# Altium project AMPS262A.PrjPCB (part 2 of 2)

## Sheet AMPS262A_SPDIF_I2S_PSIA.SchDoc
size A2; Date: Not shown in title block; ApprovedBy: Not shown in title block; CheckedBy: Not shown in title block; Author: Not shown in title block; CompanyName: Not shown in title block; Engineer: Not shown in title block; Organization: Not shown in title block; Address1: Not shown in title block; Address2: Not shown in title block; Address3: Not shown in title block; Address4: Not shown in title block; DocumentNumber: 2; Revision: Use project parameter SCH_Rev; SheetNumber: 4; SheetTotal: 5; PageSetup: Record=PageOptions¦CenterHorizontal=True¦CenterVertical=True¦PrintScale=1.00¦XCorrection=1.00¦YCorrection=1.00¦PrintKind=0¦BorderSize=5000000¦LeftOffset=0¦BottomOffset=0¦Orientation=2¦PaperLength=1000¦PaperWidth=1000¦Scale=100¦PaperSource=15¦PrintQuality=600¦MediaType=1¦DitherType=10¦PaperKind=Letter¦PrintScaleMode=1
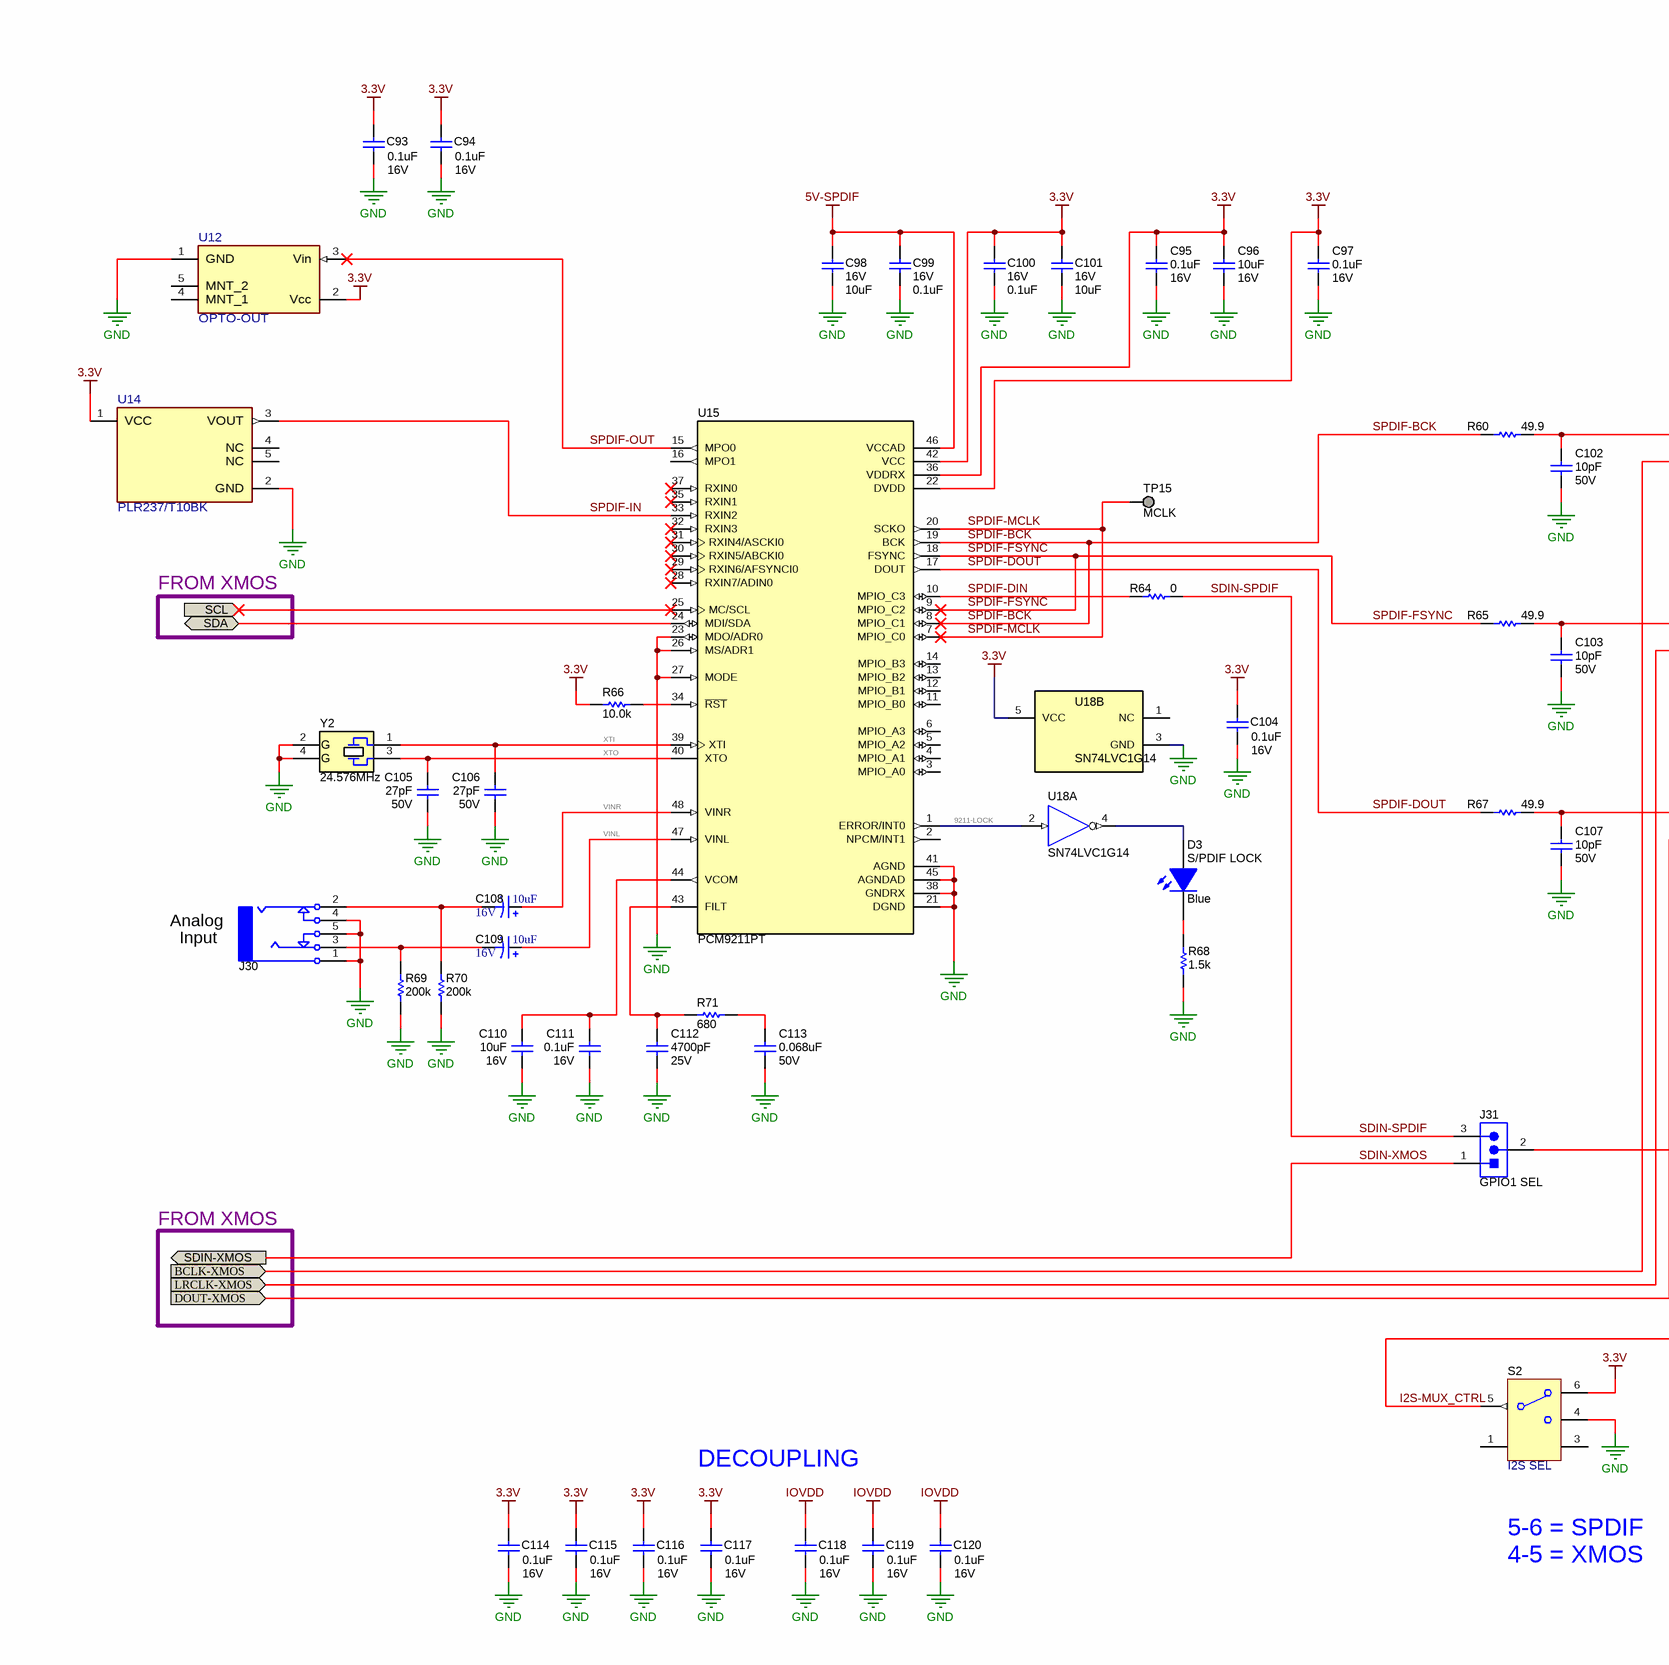
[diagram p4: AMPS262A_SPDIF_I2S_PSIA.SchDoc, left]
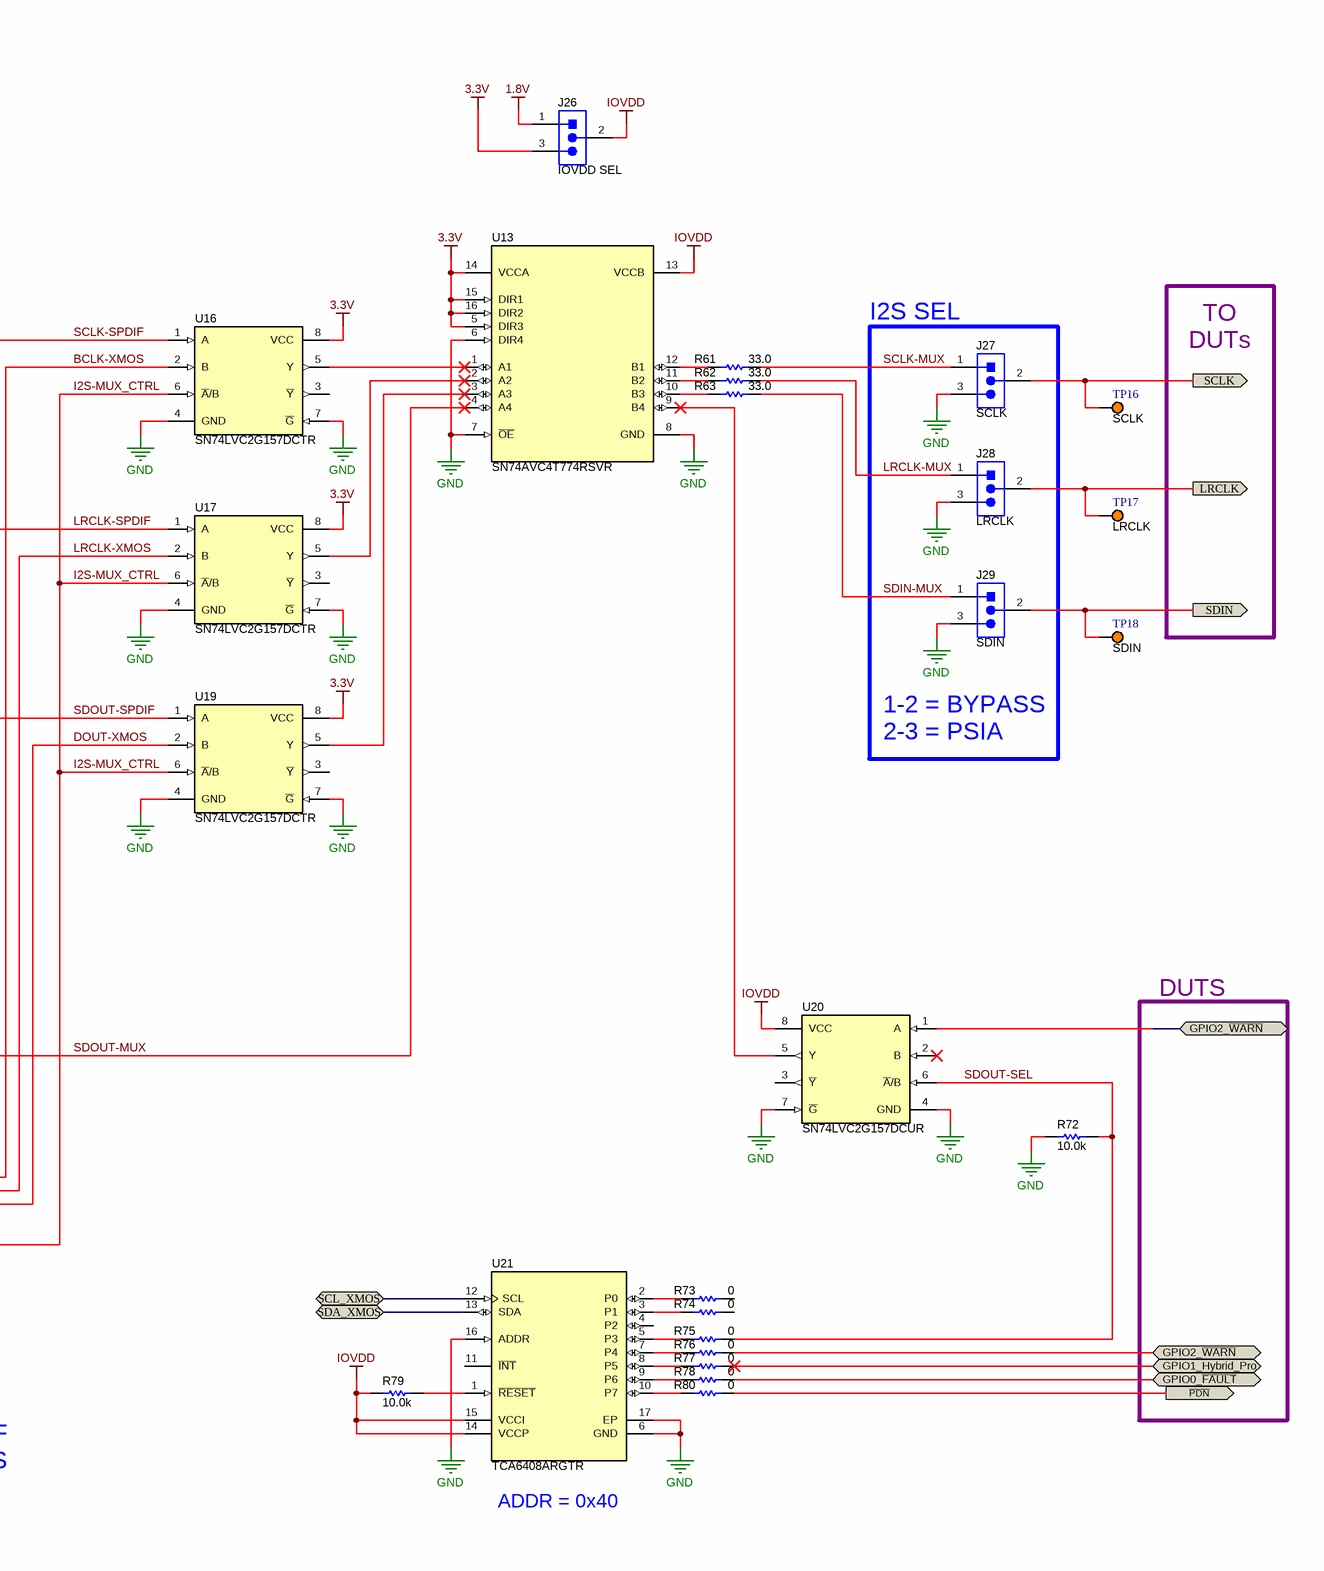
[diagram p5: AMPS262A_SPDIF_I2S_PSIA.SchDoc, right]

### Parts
C93  VDC_V: 16V  ValueDisplayed: 0.1uF  [0402L]  (hidden comment: 885012205037)
C94  VDC_V: 16V  ValueDisplayed: 0.1uF  [0402L]  (hidden comment: 885012205037)
C95  VDC_V: 16V  ValueDisplayed: 0.1uF  [0402L]  (hidden comment: 885012205037)
C96  VDC_V: 16V  ValueDisplayed: 10uF  [0603L]  (hidden comment: EMK107BBJ106MA-T)
C97  VDC_V: 16V  ValueDisplayed: 0.1uF  [0402L]  (hidden comment: 885012205037)
C98  VDC_V: 16V  ValueDisplayed: 10uF  [0603L]  (hidden comment: EMK107BBJ106MA-T)
C99  VDC_V: 16V  ValueDisplayed: 0.1uF  [0402L]  (hidden comment: 885012205037)
C100  VDC_V: 16V  ValueDisplayed: 0.1uF  [0402L]  (hidden comment: 885012205037)
C101  VDC_V: 16V  ValueDisplayed: 10uF  [0603L]  (hidden comment: EMK107BBJ106MA-T)
C102  VDC_V: 50V  ValueDisplayed: 10pF  [0402L]  (hidden comment: 885012005055)
C103  VDC_V: 50V  ValueDisplayed: 10pF  [0402L]  (hidden comment: 885012005055)
C104  VDC_V: 16V  ValueDisplayed: 0.1uF  [0402L]  (hidden comment: 885012205037)
C105  VDC_V: 50V  ValueDisplayed: 27pF  [0402L]  (hidden comment: GJM1555C1H270JB01)
C106  VDC_V: 50V  ValueDisplayed: 27pF  [0402L]  (hidden comment: GJM1555C1H270JB01)
C107  VDC_V: 50V  ValueDisplayed: 10pF  [0402L]  (hidden comment: 885012005055)
C108  VDC_V: 16V  ValueDisplayed: 10uF  [SM_RADIAL_B]  (hidden comment: EEE-FC1C100R)
C109  VDC_V: 16V  ValueDisplayed: 10uF  [SM_RADIAL_B]  (hidden comment: EEE-FC1C100R)
C110  VDC_V: 16V  ValueDisplayed: 10uF  [0603L]  (hidden comment: EMK107BBJ106MA-T)
C111  VDC_V: 16V  ValueDisplayed: 0.1uF  [0402L]  (hidden comment: 885012205037)
C112  ValueDisplayed: 4700pF  VDC_V: 25V  [0402L]  (hidden comment: CC0402KRX7R8BB472)
C113  VDC_V: 50V  ValueDisplayed: 0.068uF  [0402L]  (hidden comment: CGA2B3X7R1H683K050BB)
C114  VDC_V: 16V  ValueDisplayed: 0.1uF  [0402L]  (hidden comment: 885012205037)
C115  VDC_V: 16V  ValueDisplayed: 0.1uF  [0402L]  (hidden comment: 885012205037)
C116  VDC_V: 16V  ValueDisplayed: 0.1uF  [0402L]  (hidden comment: 885012205037)
C117  VDC_V: 16V  ValueDisplayed: 0.1uF  [0402L]  (hidden comment: 885012205037)
C118  VDC_V: 16V  ValueDisplayed: 0.1uF  [0402L]  (hidden comment: 885012205037)
C119  VDC_V: 16V  ValueDisplayed: 0.1uF  [0402L]  (hidden comment: 885012205037)
C120  VDC_V: 16V  ValueDisplayed: 0.1uF  [0402L]  (hidden comment: 885012205037)
D3  S/PDIF LOCK  value Blue  [LTST-C170TBKT_Blue]
J26  IOVDD SEL  [PBC03SAAN]
J27  SCLK  [PBC03SAAN]
J28  LRCLK  [PBC03SAAN]
J29  SDIN  [PBC03SAAN]
J30  ANA IN  [Switchcraft_35RASM]  (value not drawn)
J31  GPIO1 SEL  [PBC03SAAN]
R60  ValueDisplayed: 49.9  [0402L]  (hidden comment: Resistor)
R61  ValueDisplayed: 33.0  [0402L]  (hidden comment: ERJ-2RKF33R0X)
R62  ValueDisplayed: 33.0  [0402L]  (hidden comment: ERJ-2RKF33R0X)
R63  ValueDisplayed: 33.0  [0402L]  (hidden comment: ERJ-2RKF33R0X)
R64  ValueDisplayed: 0  [0603L]  (hidden comment: RMCF0603ZT0R00)
R65  ValueDisplayed: 49.9  [0402L]  (hidden comment: Resistor)
R66  ValueDisplayed: 10.0k  [0402L]  (hidden comment: Resistor)
R67  ValueDisplayed: 49.9  [0402L]  (hidden comment: Resistor)
R68  ValueDisplayed: 1.5k  [0603L]  (hidden comment: CRCW06031K50JNEA)
R69  ValueDisplayed: 200k  [0402L]  (hidden comment: CRCW0402200KJNED)
R70  ValueDisplayed: 200k  [0402L]  (hidden comment: CRCW0402200KJNED)
R71  ValueDisplayed: 680  [0402L]  (hidden comment: CRCW0402680RJNED)
R72  ValueDisplayed: 10.0k  [0201]  (hidden comment: Resistor)
R73  ValueDisplayed: 0  [0603L]  (hidden comment: RC0603JR-070RL)
R74  ValueDisplayed: 0  [0603L]  (hidden comment: RC0603JR-070RL)
R75  ValueDisplayed: 0  [0603L]  (hidden comment: RC0603JR-070RL)
R76  ValueDisplayed: 0  [0603L]  (hidden comment: RC0603JR-070RL)
R77  ValueDisplayed: 0  [0603L]  (hidden comment: RC0603JR-070RL)
R78  ValueDisplayed: 0  [0603L]  (hidden comment: RC0603JR-070RL)
R79  ValueDisplayed: 10.0k  [0402L]  (hidden comment: Resistor)
R80  ValueDisplayed: 0  [0603L]  (hidden comment: RC0603JR-070RL)
S2  I2S SEL  [SW_200USP1T1A1M2]
TP15  MCLK  [TP_SM_1MM]  (no BOM)
TP16  SCLK  [Keystone5003]
TP17  LRCLK  [Keystone5003]
TP18  SDIN  [Keystone5003]
U12  OPTO-OUT  [FP-FCR684208T_OTJ8-MFG]
U13  SN74AVC4T774RSVR  [RSV0016A]
U14  PLR237/T10BK  [FP-PLR237/T10BK_PTH_9MM70_13MM50-MFG]
U15  PCM9211PT  [PT0048A_N]
U16  PartNumber: SN74LVC2G157DCTR  [DCT0008A_N]  (hidden comment: 74LVC2G157DCT)
U17  PartNumber: SN74LVC2G157DCTR  [DCT0008A_N]  (hidden comment: 74LVC2G157DCT)
U18  SN74LVC1G14  [DCK0005A_N]  (parts A,B of 2)
U19  PartNumber: SN74LVC2G157DCTR  [DCT0008A_N]  (hidden comment: 74LVC2G157DCT)
U20  PartNumber: SN74LVC2G157DCUR  [DCU0008A_L]  (hidden comment: 74LVC2G157DCT)
U21  PartNumber: TCA6408ARGTR  [RGT0016A]  (hidden comment: TI-TCA6408A-QFN_RGT-16)
Y2  Frequency_Fixed: 24.576MHz  [XTAL_ABM10]  (hidden comment: ABM10-24.576MHZ-E20-T)

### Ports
BCLK-XMOS (in), DOUT-XMOS (in), GPIO0_~{FAULT} (bidir), GPIO1_Hybrid_Pro (bidir), GPIO2_~{WARN} (bidir), LRCLK (out), LRCLK-XMOS (in), SCL (in), SCL_XMOS (bidir), SCLK (out), SDA (bidir), SDA_XMOS (bidir), SDIN (out), SDIN-XMOS (out), ~{PDN} (out)

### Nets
1.8V: J26.1
3.3V: C93.1 C94.1 C95.1 C96.1 C97.1 C100.1 C101.1 C104.1 C114.1 C115.1 C116.1 C117.1 J26.3 R66.2 S2.6 U12.2(Vcc) U13.5(DIR3) U13.14(VCCA) U13.15(DIR1) U13.16(DIR2) U14.1(VCC) U15.22(DVDD) U15.36(VDDRX) U15.42(VCC) U16.8(VCC) U17.8(VCC) U18.5(VCC) U19.8(VCC)
5V-SPDIF: C98.1 C99.1 U15.46(VCCAD)
GND: C93.2 C94.2 C95.2 C96.2 C97.2 C98.2 C99.2 C100.2 C101.2 C102.2 C103.2 C104.2 C105.2 C106.2 C107.2 C110.2 C111.2 C112.2 C113.2 C114.2 C115.2 C116.2 C117.2 C118.2 C119.2 C120.2 J27.3 J28.3 J29.3 J30.1(SLEEVE) J30.4(RING_SWITCH) J30.5(TIP_SWITCH) R68.1 R69.1 R70.1 R72.1 S2.4 U12.1(GND) U13.6(DIR4) U13.7(~{OE}) U13.8(GND) U14.2(GND) U15.21(DGND) U15.23(MDO/ADR0) U15.26(MS/ADR1) U15.27(MODE) U15.38(GNDRX) U15.41(AGND) U15.45(AGNDAD) U16.4(GND) U16.7(~{G}) U17.4(GND) U17.7(~{G}) U18.3(GND) U19.4(GND) U19.7(~{G}) U20.4(GND) U20.7(~{G}) U21.6(GND) U21.16(ADDR) U21.17(EP) Y2.2(GND) Y2.4(GND)
IOVDD: C118.1 C119.1 C120.1 J26.2 R79.2 U13.13(VCCB) U20.8(VCC) U21.14(VCCP) U21.15(VCCI)
9211-LOCK: U15.1(ERROR/INT0) U18.2(A)
~{PDN}: R80.2 ; port ~{PDN}
BCLK-XMOS: U16.2(B) ; port BCLK-XMOS
DOUT-XMOS: U19.2(B) ; port DOUT-XMOS
GPIO0_~{FAULT}: R78.2 ; port GPIO0_~{FAULT}
GPIO1_Hybrid_Pro: R77.2 ; port GPIO1_Hybrid_Pro
GPIO2_~{WARN}: R76.2 U20.1(A) ; port GPIO2_~{WARN}
I2S-MUX_CTRL: S2.5(COM) U16.6(~{A}/B) U17.6(~{A}/B) U19.6(~{A}/B)
LRCLK: J28.2 TP17.1 ; port LRCLK
LRCLK-MUX: J28.1 R62.2
LRCLK-SPDIF: C103.1 R65.2 U17.1(A)
LRCLK-XMOS: U17.2(B) ; port LRCLK-XMOS
SCL: U15.25(MC/SCL) ; port SCL
SCL_XMOS: U21.12(SCL) ; port SCL_XMOS
SCLK: J27.2 TP16.1 ; port SCLK
SCLK-MUX: J27.1 R61.2
SCLK-SPDIF: C102.1 R60.2 U16.1(A)
SDA: U15.24(MDI/SDA) ; port SDA
SDA_XMOS: U21.13(SDA) ; port SDA_XMOS
SDIN: J29.2 TP18.1 ; port SDIN
SDIN-MUX: J29.1 R63.2
SDIN-SPDIF: J31.3 R64.2
SDIN-XMOS: J31.1 ; port SDIN-XMOS
SDOUT-MUX: J31.2 U13.4(A4)
SDOUT-SEL: R72.2 R75.2 U20.6(~{A}/B)
SDOUT-SPDIF: C107.1 R67.2 U19.1(A)
SPDIF-BCK: R60.1 U15.8(MPIO_C1) U15.19(BCK)
SPDIF-DIN: R64.1 U15.10(MPIO_C3)
SPDIF-DOUT: R67.1 U15.17(DOUT)
SPDIF-FSYNC: R65.1 U15.9(MPIO_C2) U15.18(FSYNC)
SPDIF-IN: U14.3(VOUT) U15.33(RXIN2)
SPDIF-MCLK: TP15.1 U15.7(MPIO_C0) U15.20(SCKO)
SPDIF-OUT: U12.3(Vin) U15.15(MPO0)
VINL: C109.1(+) U15.47(VINL)
VINR: C108.1(+) U15.48(VINR)
XTI: C106.1 U15.39(XTI) Y2.1
XTO: C105.1 U15.40(XTO) Y2.3
NetC108_2: C108.2(-) J30.2(RING) R70.2
NetC109_2: C109.2(-) J30.3(TIP) R69.2
NetC110_1: C110.1 C111.1 U15.44(VCOM)
NetC112_1: C112.1 R71.1 U15.43(FILT)
NetC113_1: C113.1 R71.2
NetD3_1: D3.1(A) U18.4(Y)
NetD3_2: D3.2(K) R68.2
NetR61_1: R61.1 U13.12(B1)
NetR62_1: R62.1 U13.11(B2)
NetR63_1: R63.1 U13.10(B3)
NetR66_1: R66.1 U15.34(~{RST})
NetR73_1: R73.1 U21.2(P0)
NetR74_1: R74.1 U21.3(P1)
NetR75_1: R75.1 U21.5(P3)
NetR76_1: R76.1 U21.7(P4)
NetR77_1: R77.1 U21.8(P5)
NetR78_1: R78.1 U21.9(P6)
NetR79_1: R79.1 U21.1(~{RESET})
NetR80_1: R80.1 U21.10(P7)
NetU13_1: U13.1(A1) U16.5(Y)
NetU13_2: U13.2(A2) U17.5(Y)
NetU13_3: U13.3(A3) U19.5(Y)
NetU13_9: U13.9(B4) U20.5(Y)

Not connected (* = marked no-connect by the designer): R73 2; R74 2; S2 1 3; U12 4(MNT_1) 5(MNT_2); U14 4(NC) 5(NC); U15 2(NPCM/INT1) 3(MPIO_A0) 4(MPIO_A1) 5(MPIO_A2) 6(MPIO_A3) 11(MPIO_B0) 12(MPIO_B1) 13(MPIO_B2) 14(MPIO_B3) 16(MPO1) 28(RXIN7/ADIN0)* 29(RXIN6/AFSYNCI0)* 30(RXIN5/ABCKI0)* 31(RXIN4/ASCKI0)* 32(RXIN3)* 35(RXIN1)* 37(RXIN0)*; U16 3(~{Y}); U17 3(~{Y}); U18 1(NC); U19 3(~{Y}); U20 2(B)* 3(~{Y}); U21 4(P2) 11(~{INT})

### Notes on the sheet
- (near J27) I2S SEL
- TO
- DUTs
- FROM XMOS
- 1-2 = BYPASS
- 2-3 = PSIA
- Analog
- Input
- DUTS
- DECOUPLING
- 5-6 = SPDIF
- 4-5 = XMOS
- ADDR = 0x40

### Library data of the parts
C93-C95 C97 C99 C100 C104 C111 C114-C120 = CMP-0006228-2: CAP, CERM, 0.1 uF, 16 V, +/- 10%, X7R, 0402; Manufacturer: Wurth Elektronik; TaMin_C: -55°C; Polarized: N; SizeAreaWB_mm2: 3; Value1: Unknown; U/M: EA; Value: 0.1uF; TaMax_C: 125°C; SizeZ_mm: 0.6; SizeX_mm: 1; SizeY_mm: 0.5; Cap_Case: 0402; Cap_F: 100nF; AEC Category: Q200
C96 C98 C101 C110 = CMP-0007122-5: CAP, CERM, 10 uF, 16 V, +/- 20%, X5R, 0603; Manufacturer: Taiyo Yuden; Alternate Manufacturer: CAL-CHIP ELECTRONICS, INC.; Alternate PartNumber: GMC10X5R106M16NT; TaMin_C: -55°C; Polarized: N; SizeAreaWB_mm2: 4.68; Value1: Unknown; U/M: EA; Value: 10uF; TaMax_C: 85°C; SizeZ_mm: 1; SizeX_mm: 1.6; SizeY_mm: 0.8; Cap_Case: 0603; SizeArea_mm2: 1.28; Cap_F: 10µF; AEC Category: Q200
C102 C103 C107 = CMP-0006215-2: CAP, CERM, 10 pF, 50 V, +/- 5%, C0G/NP0, 0402; Manufacturer: Wurth Elektronik; TaMin_C: -55°C; Polarized: N; SizeAreaWB_mm2: 3; Value1: Unknown; U/M: EA; Value: 10pF; TaMax_C: 125°C; SizeZ_mm: 0.6; SizeX_mm: 1; SizeY_mm: 0.5; Cap_Case: 0402; AEC Category: Q200
C105 C106 = CMP-0006365-2: CAP, CERM, 27 pF, 50 V, +/- 5%, C0G/NP0, 0402; Manufacturer: MuRata; TaMin_C: -55°C; Polarized: N; SizeAreaWB_mm2: 3; Value1: Unknown; U/M: EA; Value: 27pF; TaMax_C: 125°C; SizeZ_mm: 0.6; SizeX_mm: 1; SizeY_mm: 0.5; Cap_Case: 0402; CompType: Capacitor; AEC Category: Q200
C108 C109 = CMP-0010644-1: CAP, AL, 10 uF, 16 V, +/- 20%, 3 ohm, SMD; Manufacturer: Panasonic; TaMin_C: -40°C; Polarized: Y; SizeAreaWB_mm2: 47.25; Value1: 3 ohm; U/M: EA; Value: 10uF; TaMax_C: 105°C; SizeZ_mm: 5.4; SizeX_mm: 5.5; SizeY_mm: 4.3; Cap_Case: B; SizeArea_mm2: 23.65; CompType: Capacitor; Cap_F: 10µF; IRMS_A: 50mA; AEC Category: Q200; ESR_ohm: 3
C112 = CMP-0860557-1: CAP, CERM, 4700 pF, 25 V,+/- 10%, X7R, 0402; Manufacturer: Yageo; Polarized: N; SizeY_mm: 0.5; Cap_Case: 0402; Green_Lifecycle: Active; Value: 4700pF; TaMin_C: -55°C; TaMax_C: 125°C; SizeZ_mm: 0.6; U/M: EA; SizeAreaWB_mm2: 3; Cap_F: 4.7nF; SizeX_mm: 1; AEC Category: Q200; Green_REACh: Passed
C113 = CMP-0006331-2: CAP, CERM, 0.068 uF, 50 V, +/- 10%, X7R, AEC-Q200 Grade 1, 0402; Manufacturer: TDK; TaMin_C: -55°C; ESR_ohm: 0.05606; Polarized: N; SizeAreaWB_mm2: 3; Value1: 0.05606 ohm; U/M: EA; TaMax_C: 125°C; SizeZ_mm: 0.6; SizeX_mm: 1; SizeY_mm: 0.5; Cap_Case: 0402; AEC Qualified: Y; Cap_F: 68nF; IRMS_A: 684.724mA; AEC Category: Q200
D3 = CMP-0002889-2: LED, Blue, SMD; PartNumber: LTST-C170TBKT; Manufacturer: Lite-On; Type: AlInGaP; Value1: W; Io_A: 20mA; Vf_V: 3.3V
J26-J29 J31 = CMP-0002334-1: Header, 100mil, 3x1, Gold, TH; Manufacturer: Sullins Connector Solutions; Green_Lifecycle: Not Set; Green_REACh: Incomplete; CNHeader: TRUE; CT: FALSE
J30 = CMP-0074987-1: Audio Jack, 3.5mm, Stereo, R/A, SMT; Manufacturer: Switchcraft; PartNumber: 35RASMT4BHNTRX; CT: True; CompType: Audio Connector; CNHeader: False
R60 R65 R67 = CMP-0026404-2: RES, 49.9, 1%, 0.063 W, AEC-Q200 Grade 0, 0402; PartNumber: CRCW040249R9FKED; Manufacturer: Vishay-Dale; Alternate PartNumber: CRCW040249R9FKEDC; Value: 49.9; Value_Code: 49R9; Power_W: 63mW; Value2: 0.063W; VDC_V: 50V; TempCo: 100 ppm/C; EIA_Code: E96; AEC Category: Q200; AEC Grade: 0; AEC Qualified: Y; SizeArea_mm2: 0.5; SizeX_mm: 1; SizeZ_mm: 0.6
R61-R63 = CMP-0026696-1: RES, 33.0, 1%, 0.1 W, 0402; Manufacturer: Panasonic; Alternate PartNumber: ERJ-U02F33R0X; Value: 33.0; Res_ohm: 33; Value_Code: 33R0; Power_W: 100mW; Value2: 0.1W; VDC_V: 50V; TempCo: 100 ppm/C; AEC Category: Q200; SizeArea_mm2: 0.5; SizeX_mm: 1; SizeZ_mm: 0.6; U/M: EA
R64 = CMP-0023343-3: RES, 0, 1%, 0.1 W, AEC-Q200 Grade 0, 0603; Manufacturer: Stackpole Electronics Inc; Power_W: 100mW; TempCo: ppm/C; U/M: EA; Value: 0; SizeX_mm: 1.6; SizeY_mm: 0.8; SizeZ_mm: 1; Value2: 0.1W; SizeArea_mm2: 1.28; AEC Qualified: Y; AEC Category: Q200
R66 R79 = CMP-0025958-3: RES, 10.0 k, 1%, 0.063 W, AEC-Q200 Grade 0, 0402; PartNumber: CRCW040210K0FKED; Manufacturer: Vishay-Dale; Value: 10.0k; Res_ohm: 10k; Value_Code: 10k0; Power_W: 63mW; Value2: 0.063W; VDC_V: 50V; TempCo: 100 ppm/C; EIA_Code: E96; SizeArea_mm2: 0.5; SizeX_mm: 1; SizeZ_mm: 0.6; AEC Category: Q200; AEC Qualified: Y; AEC Grade: 0
R68 = CMP-0025733-4: RES, 1.5 k, 5%, 0.1 W, AEC-Q200 Grade 0, 0603; Manufacturer: Vishay-Dale; Alternate PartNumber: CRCW06031K50JNEAC; Power_W: 100mW; TempCo: 200 ppm/C; Value_Code: 1k50; Value: 1.5k; EIA_Code: E24; SizeX_mm: 1.6; SizeY_mm: 0.8; SizeZ_mm: 1; Value2: 0.1W; SizeArea_mm2: 1.28; AEC Qualified: Y; VDC_V: 75V; AEC Category: Q200; AEC Grade: 0
R69 R70 = CMP-0026873-2: RES, 200 k, 5%, 0.063 W, AEC-Q200 Grade 0, 0402; Manufacturer: Vishay-Dale; Power_W: 63mW; TempCo: 200 ppm/C; Value: 200k; EIA_Code: E24; SizeX_mm: 1; SizeY_mm: 0.5; SizeZ_mm: 0.6; Value2: 0.063W; AEC Qualified: Y; VDC_V: 50V; AEC Category: Q200; AEC Grade: 0
R71 = CMP-0026962-3: RES, 680, 5%, 0.063 W, AEC-Q200 Grade 0, 0402; Manufacturer: Vishay-Dale; Power_W: 63mW; TempCo: 200 ppm/C; Value_Code: 680R; Value: 680; EIA_Code: E24; SizeX_mm: 1; SizeY_mm: 0.5; SizeZ_mm: 0.6; Value2: 0.063W; AEC Qualified: Y; VDC_V: 50V; AEC Category: Q200; AEC Grade: 0
R72 = CMP-0027262-3: RES, 10.0 k, 1%, 0.05 W, 0201; PartNumber: CRCW020110K0FKED; Manufacturer: Vishay-Dale; Value: 10.0k; Res_ohm: 10k; Value_Code: 10k0; Power_W: 50mW; Value2: 0.05W; VDC_V: 30V; TempCo: 100 ppm/C; SizeArea_mm2: 0.18; SizeX_mm: 0.6; SizeY_mm: 0.3; SizeZ_mm: 0.26; EIA_Code: E96; AEC Category: Q200; AEC Qualified: N
R73-R78 R80 = CMP-0025885-5: RES, 0, 5%, 0.1 W, 0603; Manufacturer: Yageo; Power_W: 100mW; TempCo: 200 ppm/C; Value_Code: 0000; Value: 0; EIA_Code: E24; SizeX_mm: 1.6; SizeZ_mm: 1; Value2: 0.1W; SizeArea_mm2: 1.28; AEC Qualified: N; VDC_V: 75V; AEC Category: Q200; SizeY_mm: 0.8; SizeAreaWB_mm2: 4.68
S2 = CMP-0002209-2: Switch, SPDT, On-On, 2 Pos, TH; PartNumber: 200USP1T1A1M2RE; Manufacturer: E-Switch; CurrentRating_mA: 400A; PositionCount: 2; VDC_V: 20V
TP15 = CMP-0003825-1: 1mm Test Point, SMT; Manufacturer: Any
TP16-TP18 = CMP-0055140-2: Test Point, Miniature, Orange, TH; Manufacturer: Keystone Electronics; ContactFinish: Silver; CNHeader: FALSE; CT: TRUE; Green_Lifecycle: Active; Green_REACh: Passed
U12 = CMP-0098162-1: Optical Jack Transmitter OTJ-8; PartNumber: FCR684208T; Manufacturer: Cliff Electronic Components; SizeZ_mm: 10.2mm; Power_TotalModule: 120mW; Fall Time: 20ns; Max Supply Voltage: 5.5V; Standoff Height: 0.3mm; AEC Qualified: No; Is Female: yes; Rise Time: 30ns; Min Supply Voltage: 2.7V
U13 = CMP-0066452-2: 4-Bit Dual-Supply Bus Transceiver With Configurable Voltage-Level Shifting and 3-State Outputs, RSV0016A (UQFN-16); Manufacturer: Texas Instruments; SizeAreaWB_mm2: 10.08; CompType: IC; SizeZ_mm: 0.55; AEC Qualified: N; SizeArea_mm2: 4.68; SizeY_mm: 2.6; Green_REACh: Passed; Green_Lifecycle: Active; Rating: Catalog; SizeX_mm: 1.8; AEC Category: Q200
U14 = CMP-0097438-1: Optical Receiver 25Mbps Single 650nm; Manufacturer: Everlight Electronics; SizeZ_mm: 10.3mm; Fall Time: 10ns; Max Supply Voltage: 5.5V; Min Supply Voltage: 3V; AEC Qualified: No
U15 = CMP-0028694-1: 216 kHz Digital Audio Interface Transceiver (DIX) with Stereo ADC and Routing, PCM, S / PDIF, ADC, 4.5 - 5.5V for Analog, 2.9 - 3.6V for DIX, -40 to 85 degC, 48-Pin LQFP (PT), Green (RoHS & no Sb/Br); Manufacturer: Texas Instruments; ADC Sample Rate (kSPS): 96; Power Supply(V): 4.5-5.5 for Analog, 2.9-3.6 for DIX; Control Mode: SPI, I2C, Hardware"; Jitter(ps): 50; SubFamily: Digital Audio Transceiver (Tx/Rx); Sampling Rate(Max)(kHz): 216; ADC Resolution(Bits): 24
U16 U17 U19 = CMP-0051024-2: Single 2-Line to 1-Line Data Selector/Multiplexer, DCT0008A, LARGE T&R; Alternate PartNumber: SN74LVC2G157DCUT; Manufacturer: Texas Instruments; Generic Part Number: SN74LVC2G157; SizeArea_mm2: 11.2; SizeAreaWB_mm2: 19.0; SizeX_mm: 4.0; SizeY_mm: 2.8; SizeZ_mm: 1.3; CompType: IC; 3-State Output: No; AEC Category: Q200; AEC Qualified: N; Bits(#): 2; F @ Nom Voltage(Max)(Mhz): 150; Green_Lifecycle: Active; Green_REACh: Passed; ICC @ Nom Voltage(Max)(mA): 0.01; Input Type: CMOS/TTL; Logic: True; Output Drive (IOL/IOH)(Max)(mA): 32/-32; Output Type: CMOS; Rating: Catalog; Specialty Logic Family: Decoder/Encoder/Multiplexer; Technology Family: LVC; tpd @ Nom Voltage(Max)(ns): 14,8,6,4; VCC(Max)(V): 5.5; VCC(Min)(V): 1.65; Voltage(Nom)(V): 1.8,2.5,3.3,5
U18 = CMP-0051641-4: Single Schmitt-Trigger Inverter, DCK0005A (SOT-SC70-5); Manufacturer: Texas Instruments; Alternate PartNumber: SN74LVC1G14DCKT; PartNumber: SN74LVC1G14DCKR; Output Drive (IOL/IOH)(Max)(mA): 32/-32; Schmitt Trigger: Yes; Logic: Inverting; Bits(#): 1; Rating: Catalog; tpd @ Nom Voltage(Max)(ns): 11,6.5,5.5,5; Voltage(Nom)(V): 1.8,2.5,3.3,5; Output Type: CMOS; VCC(Min)(V): 1.65; ICC @ Nom Voltage(Max)(mA): 0.01; Input Type: CMOS/TTL; F @ Nom Voltage(Max)(Mhz): 150; VCC(Max)(V): 5.5; 3-State Output: No; AEC Category: Q200; AEC Qualified: N; CompType: IC; Green_Lifecycle: Active; Green_REACh: Passed; SizeAreaWB_mm2: 9.3; SizeArea_mm2: 4.2; SizeX_mm: 2.1; SizeY_mm: 2.0; SizeZ_mm: 1.1
U20 = CMP-0051026-2: Single 2-Line to 1-Line Data Selector/Multiplexer, DCU0008A, LARGE T&R; Alternate PartNumber: SN74LVC2G157DCUT; Manufacturer: Texas Instruments; Generic Part Number: SN74LVC2G157; CompType: IC; SizeArea_mm2: 6.4; SizeAreaWB_mm2: 12.6; SizeX_mm: 3.2; SizeY_mm: 2.0; SizeZ_mm: 0.9; 3-State Output: No; AEC Category: Q200; AEC Qualified: N; Bits(#): 2; F @ Nom Voltage(Max)(Mhz): 150; Green_Lifecycle: Active; Green_REACh: Passed; ICC @ Nom Voltage(Max)(mA): 0.01; Input Type: CMOS/TTL; Logic: True; Output Drive (IOL/IOH)(Max)(mA): 32/-32; Output Type: CMOS; Rating: Catalog; Specialty Logic Family: Decoder/Encoder/Multiplexer; Technology Family: LVC; tpd @ Nom Voltage(Max)(ns): 14,8,6,4; VCC(Max)(V): 5.5; VCC(Min)(V): 1.65; Voltage(Nom)(V): 1.8,2.5,3.3,5
U21 = CMP-0043157-2: Low-Voltage 8-Bit I2C and SMBus I/O Expander, 1.65 to 5.5 V, -40 to 85 degC, 16-pin QFN (RGT), Green (RoHS & no Sb/Br); Manufacturer: Texas Instruments; SubFamily: I2C IO Expander; No. of Outputs: 8; Interrupt Output: Yes; fSCLK(Max)(MHz): 400; VCC(Min)(V): 1.65; VCC(Max)(V): 5.5; I2C Address: 0100 00x
Y2 = CMP-0004590-3: Crystal, 24.576 MHz, 10pF, SMD; Manufacturer: Abracon Corporation; TaMin_C: -20°C; Frequency Stability: +/-20ppm; TaMax_C: 70°C

## Sheet AMPS262A_TAS5830_IO.SchDoc
size A2; Date: Not shown in title block; ApprovedBy: Not shown in title block; CheckedBy: Not shown in title block; Author: Not shown in title block; CompanyName: Not shown in title block; Engineer: Not shown in title block; Organization: Not shown in title block; Address1: Not shown in title block; Address2: Not shown in title block; Address3: Not shown in title block; Address4: Not shown in title block; DocumentNumber: 2; Revision: Use project parameter SCH_Rev; SheetNumber: 5; SheetTotal: 5; PageSetup: Record=PageOptions¦CenterHorizontal=True¦CenterVertical=True¦PrintScale=1.00¦XCorrection=1.00¦YCorrection=1.00¦PrintKind=0¦BorderSize=5000000¦LeftOffset=0¦BottomOffset=0¦Orientation=2¦PaperLength=1000¦PaperWidth=1000¦Scale=100¦PaperSource=15¦PrintQuality=600¦MediaType=1¦DitherType=10¦PaperKind=Letter¦PrintScaleMode=1
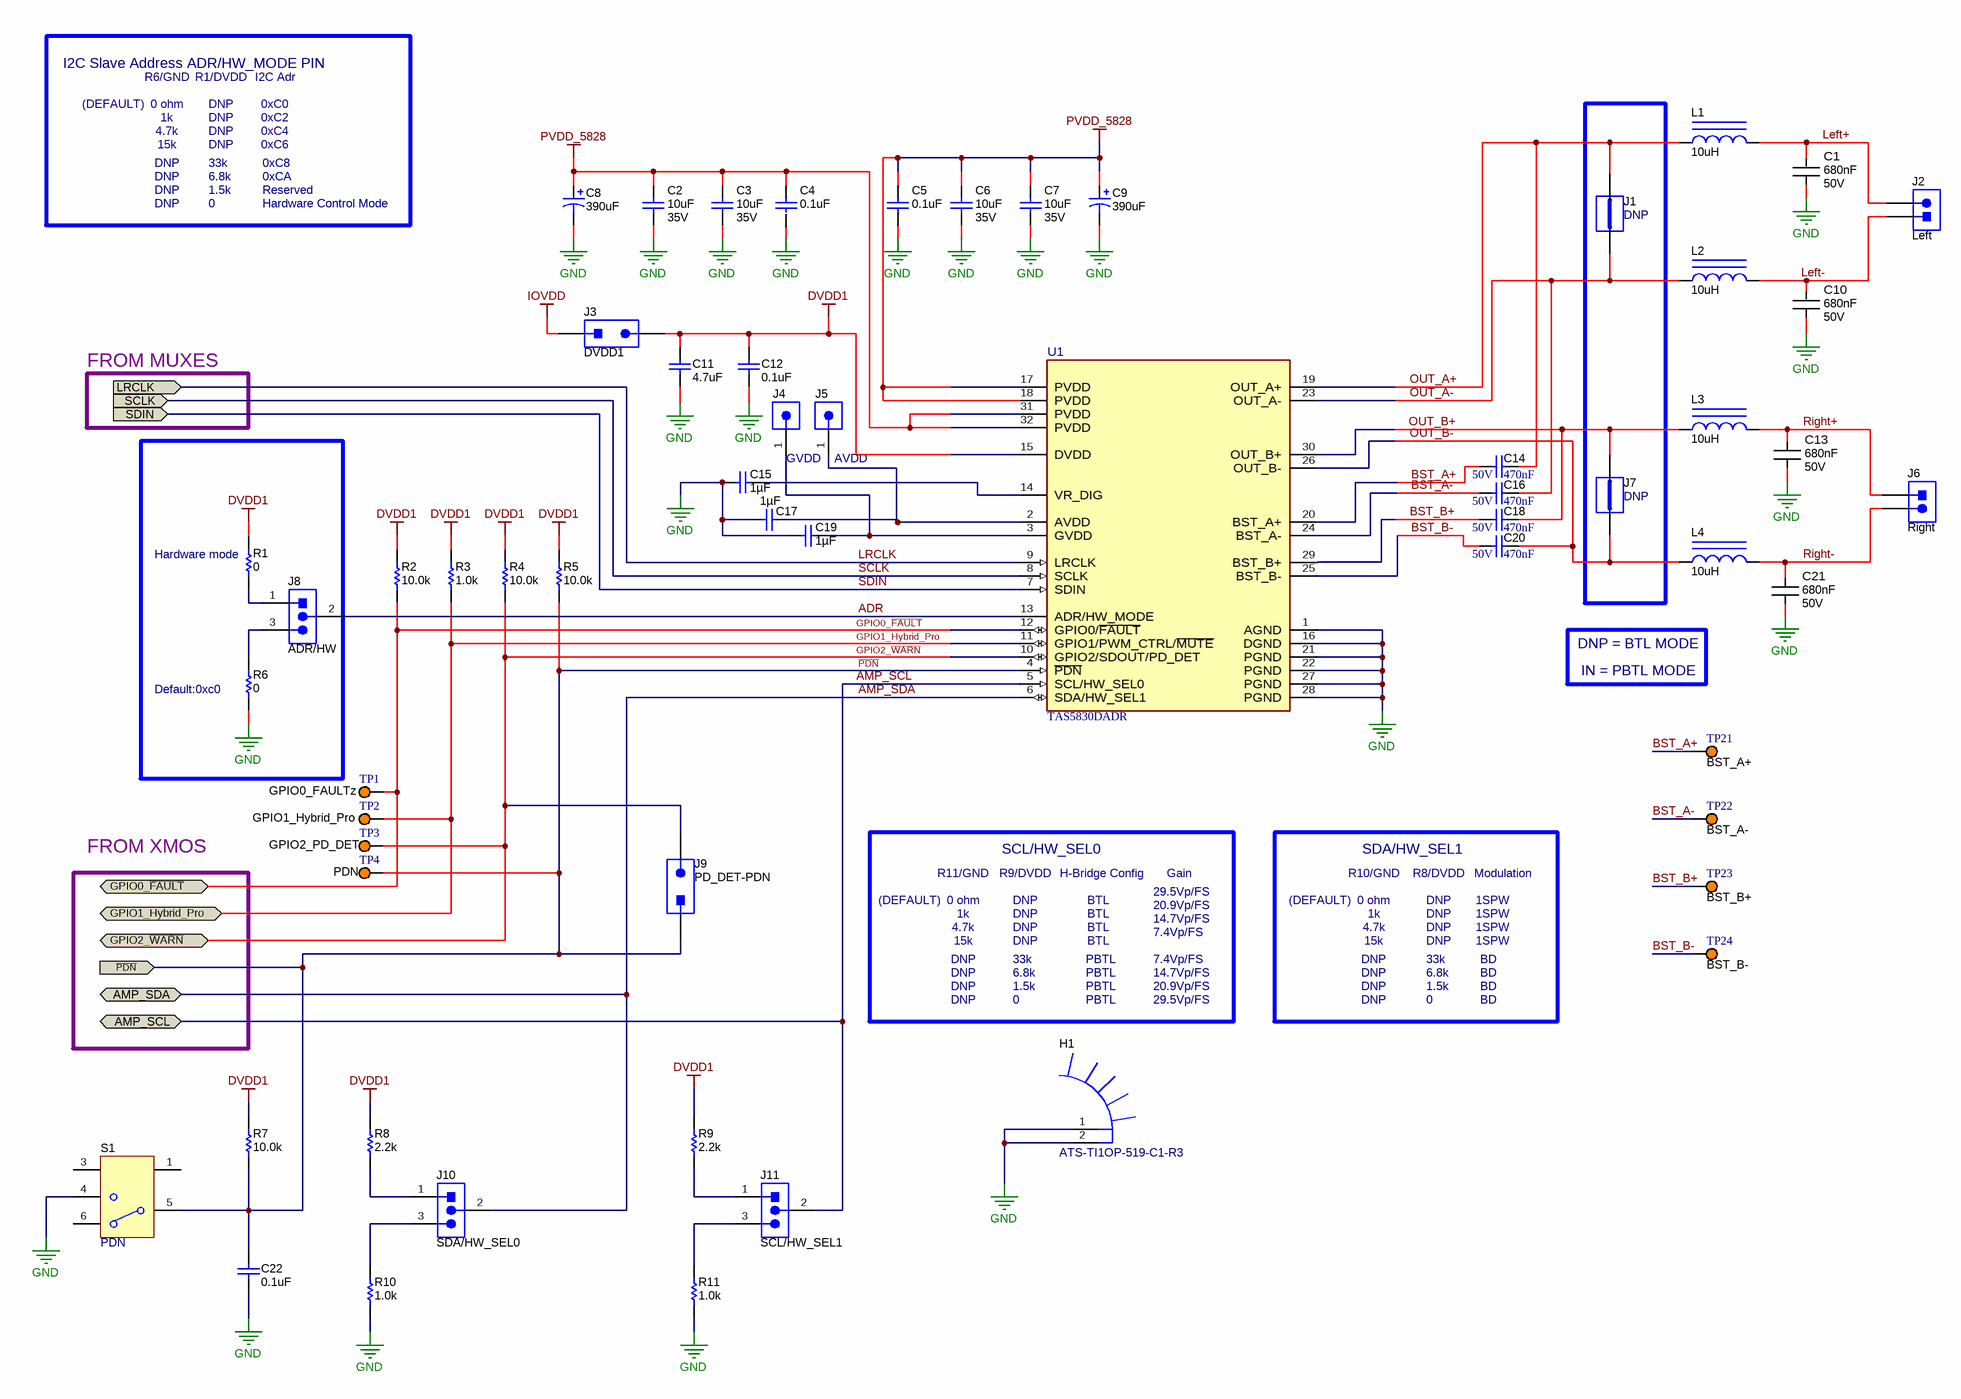
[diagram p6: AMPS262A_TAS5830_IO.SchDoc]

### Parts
C1  Cap_F: 680nF  VDC_V: 50V  [FP-CGA4J3X7R1H684M125AB_0805-MFG]  (hidden comment: CGA4J3X7R1H684M125AB)
C2  VDC_V: 35V  ValueDisplayed: 10uF  [0805L]  (hidden comment: C2012X5R1V106K085AC)
C3  VDC_V: 35V  ValueDisplayed: 10uF  [0805L]
C4  ValueDisplayed: 0.1uF  [0402L]  (hidden comment: CGA2B3X7R1H104K050BB)
C5  ValueDisplayed: 0.1uF  [0402L]  (hidden comment: CGA2B3X7R1H104K050BB)
C6  VDC_V: 35V  ValueDisplayed: 10uF  [0805L]
C7  VDC_V: 35V  ValueDisplayed: 10uF  [0805L]  (hidden comment: C2012X5R1V106K085AC)
C8  ValueDisplayed: 390uF  [SM_RADIAL_10BMM]  (hidden comment: +)
C9  ValueDisplayed: 390uF  [SM_RADIAL_10BMM]  (hidden comment: +)
C10  Cap_F: 680nF  VDC_V: 50V  [FP-CGA4J3X7R1H684M125AB_0805-MFG]  (hidden comment: CGA4J3X7R1H684M125AB)
C11  ValueDisplayed: 4.7uF  [0603L]  (hidden comment: Capacitor)
C12  ValueDisplayed: 0.1uF  [0603L]  (hidden comment: Capacitor)
C13  Cap_F: 680nF  VDC_V: 50V  [FP-CGA4J3X7R1H684M125AB_0805-MFG]  (hidden comment: CGA4J3X7R1H684M125AB)
C14  Cap_F: 470nF  VDC_V: 50V  [0603]  (hidden comment: C1608X7R1H474K080AC)
C15  ValueDisplayed: 1µF  [0603L]  (hidden comment: CL10B105MO8NNWC)
C16  Cap_F: 470nF  VDC_V: 50V  [0603]  (hidden comment: C1608X7R1H474K080AC)
C17  ValueDisplayed: 1µF  [0603L]  (hidden comment: CL10B105MO8NNWC)
C18  Cap_F: 470nF  VDC_V: 50V  [0603]  (hidden comment: C1608X7R1H474K080AC)
C19  ValueDisplayed: 1µF  [0603L]  (hidden comment: CL10B105MO8NNWC)
C20  Cap_F: 470nF  VDC_V: 50V  [0603]  (hidden comment: C1608X7R1H474K080AC)
C21  Cap_F: 680nF  VDC_V: 50V  [FP-CGA4J3X7R1H684M125AB_0805-MFG]  (hidden comment: CGA4J3X7R1H684M125AB)
C22  ValueDisplayed: 0.1uF  [0603L]  (hidden comment: Capacitor)
H1  ATS-TI1OP-519-C1-R3  [HSINK_ATS078036036-TI1OP-519-C1-R3]
J1  DNP  [HARWIN_S1911-46R]
J2  Left  [JST_B2PS-VH]
J3  DVDD1  [Sullins_PBC02SAAN]
J4  GVDD  [CONN_1040]
J5  AVDD  [CONN_1040]
J6  Right  [JST_B2PS-VH]
J7  DNP  [HARWIN_S1911-46R]
J8  ADR/HW  [PBC03SAAN]
J9  PD_DET-PDN  [Sullins_PBC02SAAN]
J10  SDA/HW_SEL0  [PBC03SAAN]
J11  SCL/HW_SEL1  [PBC03SAAN]
L1  ValueDisplayed: 10uH  [WE-PD_1210]  (hidden comment: 7447709100)
L2  ValueDisplayed: 10uH  [WE-PD_1210]  (hidden comment: 7447709100)
L3  ValueDisplayed: 10uH  [WE-PD_1210]  (hidden comment: 7447709100)
L4  ValueDisplayed: 10uH  [WE-PD_1210]  (hidden comment: 7447709100)
R1  ValueDisplayed: 0  [0603L]  (hidden comment: RC0603JR-070RL)
R2  ValueDisplayed: 10.0k  [0402L]  (hidden comment: Resistor)
R3  ValueDisplayed: 1.0k  [0402L]  (hidden comment: Resistor)
R4  ValueDisplayed: 10.0k  [0402L]  (hidden comment: Resistor)
R5  ValueDisplayed: 10.0k  [0402L]  (hidden comment: Resistor)
R6  ValueDisplayed: 0  [0603L]  (hidden comment: RC0603JR-070RL)
R7  ValueDisplayed: 10.0k  [0402L]  (hidden comment: Resistor)
R8  ValueDisplayed: 2.2k  [0603]  (hidden comment: RC0603JR-072K2L)
R9  ValueDisplayed: 2.2k  [0603]  (hidden comment: RC0603JR-072K2L)
R10  ValueDisplayed: 1.0k  [0603]  (hidden comment: RC0603JR-071KL)
R11  ValueDisplayed: 1.0k  [0603]  (hidden comment: RC0603JR-071KL)
S1  PDN  [SW_200USP1T1A1M2]
TP1  GPIO0_FAULTz  [Keystone5003]
TP2  GPIO1_Hybrid_Pro  [Keystone5003]
TP3  GPIO2_PD_DET  [Keystone5003]
TP4  PDN  [Keystone5003]
TP21  BST_A+  [Keystone5003]
TP22  BST_A-  [Keystone5003]
TP23  BST_B+  [Keystone5003]
TP24  BST_B-  [Keystone5003]
U1  TAS5830DADR  [DAD0032A-MFG]

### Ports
AMP_SCL (bidir), AMP_SDA (bidir), GPIO0_~{FAULT} (bidir), GPIO1_Hybrid_Pro (bidir), GPIO2_~{WARN} (bidir), LRCLK (in), SCLK (in), SDIN (in), ~{PDN} (in)

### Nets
DVDD1: C11.2 C12.1 J3.2 R1.2 R2.2 R3.2 R4.2 R5.2 R7.2 R8.2 R9.2 U1.15(DVDD)
GND: C1.1 C2.1 C3.1 C4.2 C5.2 C6.1 C7.1 C8.2(-) C9.2(-) C10.1 C11.1 C12.2 C13.1 C15.2 C17.2 C19.2 C21.1 C22.2 H1.1 H1.2 R6.1 R10.1 R11.1 S1.4 U1.1(AGND) U1.16(DGND) U1.21(PGND) U1.22(PGND) U1.27(PGND) U1.28(PGND)
IOVDD: J3.1
PVDD_5828: C2.2 C3.2 C4.1 C5.1 C6.2 C7.2 C8.1(+) C9.1(+) U1.17(PVDD) U1.18(PVDD) U1.31(PVDD) U1.32(PVDD)
~{PDN}: C22.1 J9.1 R5.1 R7.1 S1.5(COM) TP4.1 U1.4(~{PDN}) ; port ~{PDN}
ADR: J8.2 U1.13(ADR/HW_MODE)
AMP_SCL: J11.2 U1.5(SCL/HW_SEL0) ; port AMP_SCL
AMP_SDA: J10.2 U1.6(SDA/HW_SEL1) ; port AMP_SDA
BST_A+: C14.1 TP21.1 U1.20(BST_A+)
BST_A-: C16.1 TP22.1 U1.24(BST_A-)
BST_B+: C18.1 TP23.1 U1.29(BST_B+)
BST_B-: C20.1 TP24.1 U1.25(BST_B-)
GPIO0_~{FAULT}: R2.1 TP1.1 U1.12(GPIO0/~{FAULT}) ; port GPIO0_~{FAULT}
GPIO1_Hybrid_Pro: R3.1 TP2.1 U1.11(GPIO1/PWM_CTRL/~{MUTE}) ; port GPIO1_Hybrid_Pro
GPIO2_~{WARN}: J9.2 R4.1 TP3.1 U1.10(GPIO2/SDOUT/PD_DET) ; port GPIO2_~{WARN}
Left+: C1.2 J2.2 L1.2
Left-: C10.2 J2.1 L2.2
LRCLK: U1.9(LRCLK) ; port LRCLK
OUT_A+: C14.2 J1.2 L1.1 U1.19(OUT_A+)
OUT_A-: C16.2 J1.1 L2.1 U1.23(OUT_A-)
OUT_B+: C18.2 J7.2 L3.1 U1.30(OUT_B+)
OUT_B-: C20.2 J7.1 L4.1 U1.26(OUT_B-)
Right+: C13.2 J6.1 L3.2
Right-: C21.2 J6.2 L4.2
SCLK: U1.8(SCLK) ; port SCLK
SDIN: U1.7(SDIN) ; port SDIN
NetC15_1: C15.1 U1.14(VR_DIG)
NetC17_1: C17.1 J5.1 U1.2(AVDD)
NetC19_1: C19.1 J4.1 U1.3(GVDD)
NetJ8_1: J8.1 R1.1
NetJ8_3: J8.3 R6.2
NetJ10_1: J10.1 R8.1
NetJ10_3: J10.3 R10.2
NetJ11_1: J11.1 R9.1
NetJ11_3: J11.3 R11.2

Not connected (* = marked no-connect by the designer): S1 1 3 6

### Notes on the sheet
- (DEFAULT)
- R6/GND
- 0 ohm
- 1k
- I2C Slave Address ADR/HW_MODE PIN
- R1/DVDD
- DNP
- I2C Adr
- 0xC0
- 0xC2
- 4.7k
- 15k
- 33k
- 6.8k
- 0xC8
- 0xCA
- 0xC4
- 0xC6
- 1.5k
- 0
- Reserved
- Hardware Control Mode
- FROM MUXES
- (near R1) Hardware mode
- DNP = BTL MODE
- (near R6) Default:0xc0
- IN = PBTL MODE
- FROM XMOS
- SCL/HW_SEL0
- SDA/HW_SEL1
- R11/GND
- R9/DVDD
- BTL
- H-Bridge Config
- 29.5Vp/FS
- 20.9Vp/FS
- 14.7Vp/FS
- Gain
- R10/GND
- R8/DVDD
- 1SPW
- Modulation
- PBTL
- 7.4Vp/FS
- BD

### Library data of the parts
C1 C10 C13 C21 = CMP-0086459-1: CAP CER 0.68UF 50V X7R 0805; Manufacturer: TDK Corporation; TempCo: 15%; Symbol Name: SYM-CGA4J3X7R1H684M125AB; SizeZ_mm: 1.45mm; AEC Grade: Grade 1; Tolerance_%: 20%; AEC Qualified: Yes
C2 C7 = CMP-0007842-2: CAP, CERM, 10 uF, 35 V, +/- 10%, X5R, 0805; Manufacturer: TDK; Alternate Manufacturer: CAL-CHIP ELECTRONICS, INC.; Alternate PartNumber: GMC21X5R106K35NT; TaMin_C: -55°C; ESR_ohm: 2.818m; Polarized: N; SizeAreaWB_mm2: 6.75; Value1: 0.002818 ohm; U/M: EA; Value: 10uF; TaMax_C: 85°C; SizeZ_mm: 1.45; SizeX_mm: 2; SizeY_mm: 1.25; Cap_Case: 0805; SizeArea_mm2: 2.5; Cap_F: 10µF; IRMS_A: 3.88676A; AEC Category: Q200
C3 C6 = CMP-0007842-2: CAP, CERM, 10 uF, 35 V, +/- 10%, X5R, 0805; Manufacturer: TDK; PartNumber: C2012X5R1V106K085AC; Alternate Manufacturer: CAL-CHIP ELECTRONICS, INC.; Alternate PartNumber: GMC21X5R106K35NT; TaMin_C: -55°C; ESR_ohm: 2.818m; Polarized: N; SizeAreaWB_mm2: 6.75; Value1: 0.002818 ohm; U/M: EA; Value: 10uF; TaMax_C: 85°C; SizeZ_mm: 1.45; SizeX_mm: 2; SizeY_mm: 1.25; Cap_Case: 0805; SizeArea_mm2: 2.5; Cap_F: 10µF; IRMS_A: 3.88676A; AEC Category: Q200
C4 C5 = CMP-0006325-2: CAP, CERM, 0.1 uF, 50 V, +/- 10%, X7R, AEC-Q200 Grade 1, 0402; Manufacturer: TDK; TaMin_C: -55°C; ESR_ohm: 0.039064; Polarized: N; SizeAreaWB_mm2: 3; Value1: 0.039064 ohm; U/M: EA; Value: 0.1uF; TaMax_C: 125°C; SizeZ_mm: 0.6; SizeX_mm: 1; SizeY_mm: 0.5; Cap_Case: 0402; Value2: 50V; AEC Qualified: Y; Cap_F: 100nF; IRMS_A: 814.669mA; AEC Category: Q200
C8 C9 = CMP-0011092-1: CAP, AL, 390 uF, 35 V, +/- 20%, 0.08 ohm, SMD; PartNumber: UCL1V391MNL1GS; Manufacturer: Nichicon; Polarized: Y; CompType: Capacitor; Value: 390uF; U/M: EA; Cap_F: 390µF; VDC_V: 35V; ESR_ohm: 0.08; IRMS_A: 8.5dA; TaMin_C: -55°C; TaMax_C: 105°C; Cap_Case: 10x10; AEC Category: Q200; SizeAreaWB_mm2: 159.9; SizeArea_mm2: 113.3; SizeX_mm: 11; SizeY_mm: 10.3; SizeZ_mm: 10.2
C11 = CMP-0006949-5: CAP, CERM, 4.7 uF, 10 V, +/- 10%, X5R, 0603; PartNumber: C0603C475K8PACTU; Manufacturer: Kemet; Polarized: N; Value: 4.7uF; U/M: EA; Cap_F: 4.7µF; ESR_ohm: 6m; Value1: 0.006 ohm; VDC_V: 10V; IRMS_A: 7.24A; TaMin_C: -55°C; TaMax_C: 85°C; Cap_Case: 0603; AEC Category: Q200; SizeArea_mm2: 1.28; SizeAreaWB_mm2: 4.68; SizeX_mm: 1.6; SizeY_mm: 0.8; SizeZ_mm: 1
C12 C22 = CMP-0006860-5: CAP, CERM, 0.1 uF, 16 V, +/- 10%, X7R, 0603; PartNumber: C0603C104K4RACTU; Manufacturer: Kemet; Polarized: N; Value: 0.1uF; U/M: EA; Cap_F: 100nF; Value1: Unknown; VDC_V: 16V; TaMin_C: -55°C; TaMax_C: 125°C; Cap_Case: 0603; AEC Category: Q200; SizeArea_mm2: 1.28; SizeAreaWB_mm2: 4.68; SizeX_mm: 1.6; SizeY_mm: 0.8; SizeZ_mm: 1
C14 C16 C18 C20 = CMP-0007050-4: CAP, CERM, 0.47 uF, 50 V, +/- 10%, X7R, 0603; Manufacturer: TDK; Value: 0.47uF; TaMin_C: -55°C; ESR_ohm: 10.974m; Polarized: N; SizeAreaWB_mm2: 4.68; Value1: 0.010974 ohm; U/M: EA; TaMax_C: 125°C; SizeZ_mm: 1; SizeX_mm: 1.6; SizeY_mm: 0.8; SizeArea_mm2: 1.28; IRMS_A: 1.5748A; AEC Category: Q200
C15 C17 C19 = CMP-0082012-1: CAP, CERM, 1 µF, 16 V,+/- 20%, X7R, 0603; Manufacturer: Samsung; SizeAreaWB_mm2: 4.68; SizeArea_mm2: 1.28; AEC Qualified: N; AEC Category: Q200; Value: 1uF; TaMax_C: 125°C; SizeZ_mm: 1; TaMin_C: -55°C; VDC_V: 16V; SizeY_mm: 0.8; U/M: EA; CompType: Capacitor; SizeX_mm: 1.6; Cap_Case: 0603
H1 = CMP-0004031-2: Heat Sink, Vertical; Manufacturer: Advanced Thermal Solutions
J1 J7 = CMP-0075020-1: JUMPER TIN SMD; Manufacturer: Harwin; PartNumber: S1911-46R; CNHeader: False; Green_Lifecycle: Active; Green_REACh: Passed; CompType: Jumper SMT
J2 J6 = CMP-0074989-1: Header (friction lock), 3.96mm, 2x1, Tin, R/A, TH; Manufacturer: JST Manufacturing; PartNumber: B2PS-VH(LF)(SN); Alternate Manufacturer: JST Sales America Inc.; Alternate PartNumber: S2P-VH(LF)(SN); CNHeader: False; Green_Lifecycle: Active; Green_REACh: Passed
J3 J9 = CMP-0054566-1: Header, 100mil, 2x1, Gold, TH; PartNumber: PBC02SAAN; Manufacturer: Sullins Connector Solutions; Pitch_mm: 2.54; Gender: Male; Shrouded: N; Row_Count: 1; Current_A: 3A; Voltage_V: 1.8kV; Cert_UL: Y; CNHeader: TRUE; CT: FALSE; Green_Lifecycle: Active; Green_REACh: Passed
J4 J5 = CMP-0055161-1: Manufacturer: Keystone; PartNumber: 1040; CNHeader: FALSE; Green_Lifecycle: Active; Green_REACh: Passed; CompType: Test Point; CT: TRUE
J8 J10 J11 = CMP-0002334-1: as J26-J29 on sheet AMPS262A_SPDIF_I2S_PSIA
L1-L4 = CMP-0064206-1: Inductor, Shielded Drum Core, Ferrite, 10 uH, 7.1 A, 0.01294 ohm, SMD; Manufacturer: Wurth Elektronik; Isat: 10.5A @ 10% inductance drop; Irms: 7.1A @ 40C rise; Green_Lifecycle: Active; SizeAreaWB_mm2: 196; Green_REACh: Passed; Value: 10uH; Imax_A: 7.1A; SizeZ_mm: 10; SizeX_mm: 12; SizeArea_mm2: 144; Ind_H: 10µH; AEC Category: Q200
R1 R6 = CMP-0025885-5: as R73-R78 on sheet AMPS262A_SPDIF_I2S_PSIA
R2 = CMP-0065359-1: RES, 15.0 k, .1%, .063 W, AEC-Q200 Grade 0, 0402; PartNumber: ERA-2AEB153X; Manufacturer: Panasonic; Value: 15.0k; Res_ohm: 15k; Value_Code: 15k0; Tolerance_%: 0.1%; Power_W: 63mW; Value2: .063W; VDC_V: 50V; TempCo: 25 ppm/C; EIA_Code: E192; U/M: EA; SizeArea_mm2: 0.5; SizeX_mm: 1.0; SizeZ_mm: 0.6; AEC Category: Q200; AEC Qualified: Y; AEC Grade: 0
R3 = CMP-0026852-3: RES, 1.0 k, 5%, 0.063 W, AEC-Q200 Grade 0, 0402; PartNumber: CRCW04021K00JNED; Manufacturer: Vishay-Dale; Alternate Manufacturer: Vishay Dale; Alternate PartNumber: CRCW04021K00JNTD; Value: 1.0k; Res_ohm: 1k; Value_Code: 1k00; Power_W: 63mW; Value2: 0.063W; VDC_V: 50V; TempCo: 200 ppm/C; EIA_Code: E24; AEC Category: Q200; AEC Qualified: Y; AEC Grade: 0; SizeArea_mm2: 0.5; SizeX_mm: 1; SizeZ_mm: 0.6
R4 R5 R7 = CMP-0025958-3: as R66 on sheet AMPS262A_SPDIF_I2S_PSIA
R8 R9 = CMP-0025906-5: RES, 2.2 k, 5%, 0.1 W, 0603; Manufacturer: Yageo; Power_W: 100mW; TempCo: 100 ppm/C; Value_Code: 2k20; Value: 2.2k; EIA_Code: E24; SizeX_mm: 1.6; SizeY_mm: 0.8; SizeZ_mm: 1; Value2: 0.1W; SizeArea_mm2: 1.28; VDC_V: 75V; SizeAreaWB_mm2: 4.68; AEC Qualified: N; AEC Category: Q200
R10 R11 = CMP-0025899-5: RES, 1.0 k, 5%, 0.1 W, 0603; Manufacturer: Yageo; Power_W: 100mW; TempCo: 100 ppm/C; Value_Code: 1k00; Value: 1.0k; EIA_Code: E24; Res_ohm: 1k; SizeX_mm: 1.6; SizeY_mm: 0.8; SizeZ_mm: 1; Value2: 0.1W; SizeArea_mm2: 1.28; AEC Qualified: N; VDC_V: 75V; AEC Category: Q200; SizeAreaWB_mm2: 4.68
S1 = CMP-0002209-2: as S2 on sheet AMPS262A_SPDIF_I2S_PSIA
TP1-TP4 TP21-TP24 = CMP-0055140-2: as TP16-TP18 on sheet AMPS262A_SPDIF_I2S_PSIA
U1 = CMP-0124450-1: Manufacturer: Texas Instruments; Standoff Height: 0.05mm; SizeZ_mm: 1.15mm

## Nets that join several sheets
1.8V: AMPS262A_USB (6 pins), AMPS262A_SPDIF_I2S_PSIA (J26.1)
3.3V: AMPS262A_PowerSupplies (5 pins), AMPS262A_USB (57 pins), AMPS262A_SPDIF_I2S_PSIA (28 pins)
5V-SPDIF: AMPS262A_PowerSupplies (R31.1), AMPS262A_USB (L7.2), AMPS262A_SPDIF_I2S_PSIA (C98.1 C99.1 U15.46)
GND: AMPS262A_PowerSupplies (39 pins), AMPS262A_USB (71 pins), AMPS262A_SPDIF_I2S_PSIA (63 pins), AMPS262A_TAS5830_IO (30 pins)
IOVDD: AMPS262A_USB (C79.2 C80.2 R39.2 U7.3), AMPS262A_SPDIF_I2S_PSIA (9 pins), AMPS262A_TAS5830_IO (J3.1)
PVDD_5828: AMPS262A_PowerSupplies (J14.2 J18.2), AMPS262A_TAS5830_IO (12 pins)
~{PDN}: AMPS262A_SPDIF_I2S_PSIA (R80.2), AMPS262A_TAS5830_IO (7 pins)
AMP_SCL: AMPS262A_USB (J22.1 TP19.1), AMPS262A_TAS5830_IO (J11.2 U1.5)
AMP_SDA: AMPS262A_USB (J23.1 TP20.1), AMPS262A_TAS5830_IO (J10.2 U1.6)
BCLK-XMOS: AMPS262A_USB (R43.2 R52.2), AMPS262A_SPDIF_I2S_PSIA (U16.2)
DOUT-XMOS: AMPS262A_USB (R47.2), AMPS262A_SPDIF_I2S_PSIA (U19.2)
GPIO0_~{FAULT}: AMPS262A_SPDIF_I2S_PSIA (R78.2), AMPS262A_TAS5830_IO (R2.1 TP1.1 U1.12)
GPIO1_Hybrid_Pro: AMPS262A_PowerSupplies (J16.1 R28.2), AMPS262A_SPDIF_I2S_PSIA (R77.2), AMPS262A_TAS5830_IO (R3.1 TP2.1 U1.11)
GPIO2_~{WARN}: AMPS262A_SPDIF_I2S_PSIA (R76.2 U20.1), AMPS262A_TAS5830_IO (J9.2 R4.1 TP3.1 U1.10)
LRCLK: AMPS262A_SPDIF_I2S_PSIA (J28.2 TP17.1), AMPS262A_TAS5830_IO (U1.9)
LRCLK-XMOS: AMPS262A_USB (R42.2), AMPS262A_SPDIF_I2S_PSIA (U17.2)
SCL: AMPS262A_USB (R37.2 U6.37 U7.8), AMPS262A_SPDIF_I2S_PSIA (U15.25)
SCL_XMOS: AMPS262A_USB (J22.2 TP13.1 U7.5 U8.12), AMPS262A_SPDIF_I2S_PSIA (U21.12)
SCLK: AMPS262A_SPDIF_I2S_PSIA (J27.2 TP16.1), AMPS262A_TAS5830_IO (U1.8)
SDA: AMPS262A_USB (R38.2 U6.38 U7.1), AMPS262A_SPDIF_I2S_PSIA (U15.24)
SDA_XMOS: AMPS262A_USB (J23.2 TP14.1 U7.4 U8.13), AMPS262A_SPDIF_I2S_PSIA (U21.13)
SDIN: AMPS262A_SPDIF_I2S_PSIA (J29.2 TP18.1), AMPS262A_TAS5830_IO (U1.7)
SDIN-XMOS: AMPS262A_USB (R44.2), AMPS262A_SPDIF_I2S_PSIA (J31.1)

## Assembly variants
001: not fitted FID1 FID2 FID3 FID4 FID5 FID6 J1 J7 J14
